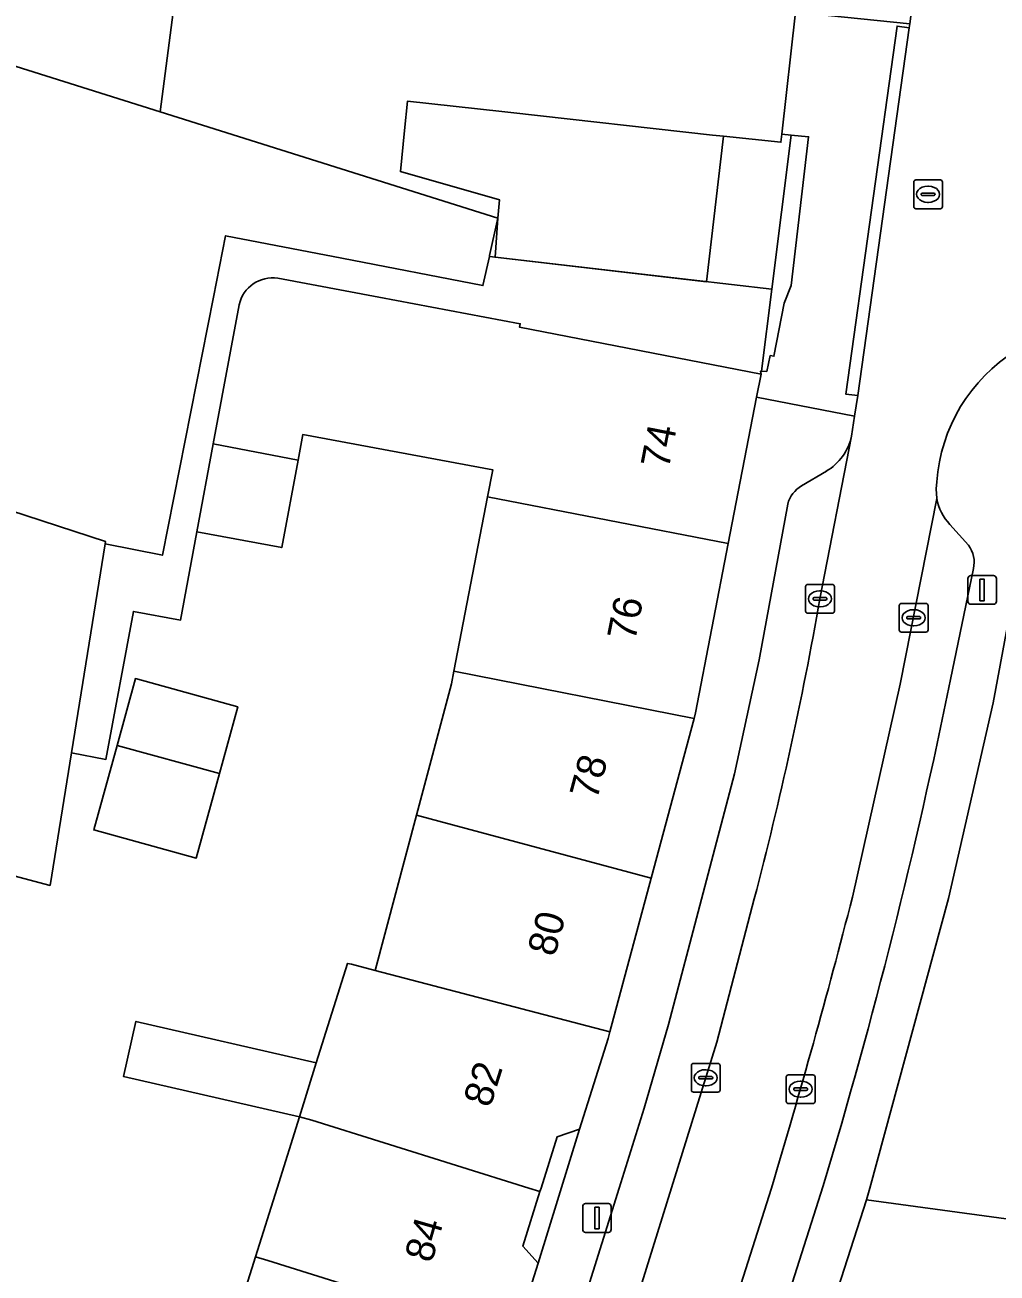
# Model space of a CAD drawing. Extents: x 161838 to 162344, y 381620 to 382160.
# Drawn here: x 161903.48 to 161937.3, y 381747.04 to 381790.47 of the extents above; entities that cross this region are included whole.
import ezdxf

# ---------------------------------------------------------------- set-up
doc = ezdxf.new("R2010")
doc.units = 0
for name, color, linetype in [('IMGEO_Erf', 7, 'Continuous'), ('IMGEO_Kolk', 7, 'Continuous'), ('IMGEO_Lichtmast', 7, 'Continuous'), ('IMGEO_Pand', 7, 'Continuous'), ('IMGEO_Pand_nummerreeks', 7, 'Continuous'), ('IMGEO_Pand_overbouw', 7, 'Continuous'), ('IMGEO_Parkeervlak_open', 7, 'Continuous'), ('IMGEO_Rijbaan_lokaal_open', 7, 'Continuous'), ('IMGEO_Rioolput', 7, 'Continuous'), ('IMGEO_Voetpad_open', 7, 'Continuous')]:
    doc.layers.add(name, color=color, linetype=linetype)

msp = doc.modelspace()

# ---------------------------------------------------------------- linework, layer by layer
at = {"layer": 'IMGEO_Erf'}
for points in [[(161930.143, 381786.634), (161929.815, 381786.663), (161929.784, 381786.389), (161927.782, 381786.601), (161927.396, 381786.639), (161920.39, 381787.417), (161920.074, 381787.452), (161916.79, 381787.816), (161916.687, 381786.798), (161916.543, 381785.369), (161919.986, 381784.388), (161919.939, 381783.745), (161919.647, 381782.443), (161919.639, 381782.409), (161929.463, 381781.27)], [(161905.878, 381762.46), (161906.688, 381765.402), (161907.326, 381767.725), (161910.889, 381766.746), (161910.25, 381764.423), (161909.441, 381761.48)], [(161921.4, 381749.878), (161920.799, 381747.972), (161921.338, 381747.387), (161922.777, 381752.053), (161922.002, 381751.786), (161921.439, 381750)]]:
    msp.add_lwpolyline(points, close=True, dxfattribs=at)
for points in [[(162000, 381769.681), (161974.073, 381772.99), (161973.465, 381773.068), (161939.385, 381777.509), (161939.117, 381777.363), (161937.166, 381766.879), (161935.609, 381760.072), (161932.874, 381750), (161932.761, 381749.584), (161940.003, 381748.598), (161940.179, 381750), (161940.747, 381754.512), (161939.055, 381754.703), (161940.656, 381766.246), (161941.27, 381771.689), (161943.773, 381771.406), (161958.15, 381769.783), (161958.302, 381771.128), (161966.661, 381770.185), (161965.98, 381765.232), (161963.918, 381750), (161962.379, 381738.634)], [(161910.729, 381745.136), (161911.501, 381747.601), (161912.253, 381750), (161913.031, 381752.482), (161906.907, 381753.886), (161907.345, 381755.798), (161913.619, 381754.359), (161914.701, 381757.815), (161914.848, 381757.787), (161915.662, 381757.574), (161917.1, 381762.969), (161918.319, 381767.543), (161918.404, 381767.982), (161919.577, 381774.046), (161919.76, 381774.989), (161913.149, 381776.217), (161912.983, 381775.322), (161912.418, 381772.284), (161909.468, 381772.836), (161908.896, 381769.76), (161907.257, 381770.065), (161906.301, 381764.916), (161905.101, 381765.139), (161904.357, 381760.527), (161891.624, 381763.915)]]:
    msp.add_lwpolyline(points, dxfattribs=at)
at = {"layer": 'IMGEO_Kolk'}
for p, q in [((161930.714, 381771.001), (161931.566, 381771.001)), ((161930.639, 381770.075), (161930.639, 381770.927)), ((161931.127, 381770.781), (161931.152, 381770.781)), ((161931.64, 381770.927), (161931.64, 381770.075)), ((161930.898, 381770.495), (161930.898, 381770.507)), ((161931.336, 381770.458), (161930.938, 381770.458)), ((161930.941, 381770.544), (161931.339, 381770.544)), ((161931.15, 381770.221), (161931.125, 381770.221)), ((161931.382, 381770.507), (161931.382, 381770.495)), ((161933.898, 381769.417), (161933.898, 381770.269)), ((161933.973, 381770.343), (161934.825, 381770.343)), ((161934.899, 381770.269), (161934.899, 381769.417)), ((161931.566, 381770.001), (161930.714, 381770.001)), ((161934.157, 381769.837), (161934.157, 381769.849)), ((161934.595, 381769.8), (161934.197, 381769.8)), ((161934.2, 381769.886), (161934.598, 381769.886)), ((161934.386, 381770.123), (161934.411, 381770.123)), ((161934.641, 381769.849), (161934.641, 381769.837)), ((161934.825, 381769.343), (161933.973, 381769.343)), ((161934.409, 381769.563), (161934.384, 381769.563)), ((161926.665, 381753.411), (161926.665, 381754.263)), ((161926.74, 381754.337), (161927.592, 381754.337)), ((161927.153, 381754.117), (161927.178, 381754.117)), ((161927.666, 381754.263), (161927.666, 381753.411)), ((161926.924, 381753.831), (161926.924, 381753.843)), ((161927.362, 381753.794), (161926.964, 381753.794)), ((161926.967, 381753.88), (161927.365, 381753.88)), ((161927.408, 381753.843), (161927.408, 381753.831)), ((161929.967, 381753.013), (161929.967, 381753.865)), ((161930.042, 381753.939), (161930.894, 381753.939)), ((161930.455, 381753.719), (161930.48, 381753.719)), ((161930.968, 381753.865), (161930.968, 381753.013)), ((161927.592, 381753.337), (161926.74, 381753.337)), ((161927.176, 381753.557), (161927.151, 381753.557)), ((161930.226, 381753.433), (161930.226, 381753.445)), ((161930.664, 381753.396), (161930.266, 381753.396)), ((161930.269, 381753.482), (161930.667, 381753.482)), ((161930.71, 381753.445), (161930.71, 381753.433)), ((161930.894, 381752.939), (161930.042, 381752.939)), ((161930.478, 381753.159), (161930.453, 381753.159))]:
    msp.add_line(p, q, dxfattribs=at)
for points in [[(161930.714, 381771.001), (161931.566, 381771.001)], [(161930.639, 381770.075), (161930.639, 381770.927)], [(161931.64, 381770.927), (161931.64, 381770.075)], [(161933.898, 381769.417), (161933.898, 381770.269)], [(161933.973, 381770.343), (161934.825, 381770.343)], [(161934.899, 381770.269), (161934.899, 381769.417)], [(161931.566, 381770.001), (161930.714, 381770.001)], [(161934.825, 381769.343), (161933.973, 381769.343)], [(161926.665, 381753.411), (161926.665, 381754.263)], [(161926.74, 381754.337), (161927.592, 381754.337)], [(161927.666, 381754.263), (161927.666, 381753.411)], [(161929.967, 381753.013), (161929.967, 381753.865)], [(161930.042, 381753.939), (161930.894, 381753.939)], [(161930.968, 381753.865), (161930.968, 381753.013)], [(161927.592, 381753.337), (161926.74, 381753.337)], [(161930.894, 381752.939), (161930.042, 381752.939)]]:
    msp.add_lwpolyline(points, dxfattribs=at)
for centre, radius, start, end in [((161930.716, 381770.925), 0.0765, 91.552, 178.448), ((161930.716, 381770.925), 0.0765, 91.552, 178.448), ((161931.564, 381770.925), 0.0765, 1.552, 88.448), ((161931.564, 381770.925), 0.0765, 1.552, 88.448), ((161930.938, 381770.504), 0.0403, 85.8775, 175.7526), ((161930.935, 381770.494), 0.0366, 178.938, 274.7102), ((161931.339, 381770.501), 0.043, 264.8664, 352.4533), ((161931.343, 381770.506), 0.0386, 1.7309, 96.639), ((161933.975, 381770.267), 0.0765, 91.552, 178.448), ((161933.975, 381770.267), 0.0765, 91.552, 178.448), ((161934.823, 381770.267), 0.0765, 1.552, 88.448), ((161934.823, 381770.267), 0.0765, 1.552, 88.448), ((161930.716, 381770.077), 0.0765, 181.552, 268.448), ((161930.716, 381770.077), 0.0765, 181.552, 268.448), ((161931.564, 381770.077), 0.0765, 271.552, 358.448), ((161931.564, 381770.077), 0.0765, 271.552, 358.448), ((161934.197, 381769.846), 0.0403, 85.8775, 175.7526), ((161934.194, 381769.836), 0.0366, 178.938, 274.7102), ((161934.598, 381769.843), 0.043, 264.8664, 352.4533), ((161934.602, 381769.848), 0.0386, 1.7309, 96.639), ((161933.975, 381769.419), 0.0765, 181.552, 268.448), ((161933.975, 381769.419), 0.0765, 181.552, 268.448), ((161934.823, 381769.419), 0.0765, 271.552, 358.448), ((161934.823, 381769.419), 0.0765, 271.552, 358.448), ((161926.742, 381754.261), 0.0765, 91.552, 178.448), ((161926.742, 381754.261), 0.0765, 91.552, 178.448), ((161927.59, 381754.261), 0.0765, 1.552, 88.448), ((161927.59, 381754.261), 0.0765, 1.552, 88.448), ((161926.964, 381753.84), 0.0403, 85.8775, 175.7526), ((161926.961, 381753.83), 0.0366, 178.938, 274.7102), ((161927.365, 381753.837), 0.043, 264.8664, 352.4533), ((161927.369, 381753.842), 0.0386, 1.7309, 96.639), ((161930.044, 381753.863), 0.0765, 91.552, 178.448), ((161930.044, 381753.863), 0.0765, 91.552, 178.448), ((161930.892, 381753.863), 0.0765, 1.552, 88.448), ((161930.892, 381753.863), 0.0765, 1.552, 88.448), ((161926.742, 381753.413), 0.0765, 181.552, 268.448), ((161926.742, 381753.413), 0.0765, 181.552, 268.448), ((161927.59, 381753.413), 0.0765, 271.552, 358.448), ((161927.59, 381753.413), 0.0765, 271.552, 358.448), ((161930.266, 381753.442), 0.0403, 85.8775, 175.7526), ((161930.263, 381753.432), 0.0366, 178.938, 274.7102), ((161930.667, 381753.439), 0.043, 264.8664, 352.4533), ((161930.671, 381753.444), 0.0386, 1.7309, 96.639), ((161930.044, 381753.015), 0.0765, 181.552, 268.448), ((161930.044, 381753.015), 0.0765, 181.552, 268.448), ((161930.892, 381753.015), 0.0765, 271.552, 358.448), ((161930.892, 381753.015), 0.0765, 271.552, 358.448)]:
    msp.add_arc(centre, radius, start, end, dxfattribs=at)
for centre, major_axis, ratio, start_param, end_param in [((161931.126, 381770.501), (-0.387, 0.002), 0.722429, 4.712389, 7.853982), ((161931.151, 381770.501), (-0.39, 0.002), 0.717154, 1.570796, 4.712389), ((161934.385, 381769.843), (-0.387, 0.002), 0.722429, 4.712389, 7.853982), ((161934.41, 381769.843), (-0.39, 0.002), 0.717154, 1.570796, 4.712389), ((161927.152, 381753.837), (-0.387, 0.002), 0.722429, 4.712389, 7.853982), ((161927.177, 381753.837), (-0.39, 0.002), 0.717154, 1.570796, 4.712389), ((161930.454, 381753.439), (-0.387, 0.002), 0.722429, 4.712389, 7.853982), ((161930.479, 381753.439), (-0.39, 0.002), 0.717154, 1.570796, 4.712389)]:
    msp.add_ellipse(centre, major_axis=major_axis, ratio=ratio, start_param=start_param, end_param=end_param, dxfattribs=at)
at = {"layer": 'IMGEO_Lichtmast'}
for p, q in [((161936.286, 381770.41), (161936.286, 381771.21)), ((161936.286, 381771.21), (161936.286, 381770.41)), ((161936.386, 381771.31), (161937.176, 381771.31)), ((161937.176, 381771.31), (161936.386, 381771.31)), ((161937.276, 381771.21), (161937.276, 381770.41)), ((161937.276, 381770.41), (161937.276, 381771.21)), ((161937.176, 381770.31), (161936.386, 381770.31)), ((161936.386, 381770.31), (161937.176, 381770.31)), ((161922.888, 381748.558), (161922.888, 381749.358)), ((161922.888, 381749.358), (161922.888, 381748.558)), ((161922.988, 381749.458), (161923.778, 381749.458)), ((161923.778, 381749.458), (161922.988, 381749.458)), ((161923.878, 381749.358), (161923.878, 381748.558)), ((161923.878, 381748.558), (161923.878, 381749.358)), ((161923.778, 381748.458), (161922.988, 381748.458)), ((161922.988, 381748.458), (161923.778, 381748.458))]:
    msp.add_line(p, q, dxfattribs=at)
for points in [[(161936.706, 381771.185), (161936.856, 381771.185), (161936.856, 381770.435), (161936.706, 381770.435), (161936.706, 381771.185)], [(161923.308, 381749.333), (161923.458, 381749.333), (161923.458, 381748.583), (161923.308, 381748.583), (161923.308, 381749.333)]]:
    msp.add_lwpolyline(points, dxfattribs=at)
for centre, start, end in [((161936.386, 381771.21), 90, 180), ((161936.386, 381771.21), 90, 180), ((161937.176, 381771.21), 0, 90), ((161937.176, 381771.21), 360, 90), ((161936.386, 381770.41), 180, 270), ((161936.386, 381770.41), 180, 270), ((161937.176, 381770.41), 270, 0), ((161937.176, 381770.41), 270, 0), ((161922.988, 381749.358), 90, 180), ((161922.988, 381749.358), 90, 180), ((161923.778, 381749.358), 0, 90), ((161923.778, 381749.358), 360, 90), ((161922.988, 381748.558), 180, 270), ((161922.988, 381748.558), 180, 270), ((161923.778, 381748.558), 270, 0), ((161923.778, 381748.558), 270, 0)]:
    msp.add_arc(centre, 0.1, start, end, dxfattribs=at)
at = {"layer": 'IMGEO_Pand'}
for points in [[(161911.591, 381813.594), (161887.08, 381818.184), (161882.7, 381795.067), (161891.426, 381793.391), (161891.237, 381792.79), (161908.185, 381787.449)], [(161919.939, 381783.745), (161908.185, 381787.449), (161891.237, 381792.79), (161891.426, 381793.391), (161882.7, 381795.067), (161881.558, 381789.042), (161880.152, 381781.62), (161884.545, 381780.782), (161884.571, 381780.917), (161887.782, 381780.305), (161887.441, 381778.645), (161906.287, 381772.495), (161906.273, 381772.411), (161908.264, 381772.019), (161910.041, 381780.996), (161910.464, 381783.132), (161914.505, 381782.351), (161919.414, 381781.401), (161919.639, 381782.409), (161919.647, 381782.443)], [(161887.441, 381778.645), (161887.782, 381780.305), (161884.571, 381780.917), (161884.545, 381780.782), (161880.152, 381781.62), (161880.122, 381781.461), (161877.48, 381767.677), (161886.792, 381765.2), (161891.624, 381763.915), (161904.357, 381760.527), (161905.101, 381765.139), (161906.273, 381772.411), (161906.287, 381772.495)], [(161910.036, 381775.892), (161909.468, 381772.836), (161912.418, 381772.284), (161912.983, 381775.322)], [(161926.758, 381766.342), (161926.809, 381766.533), (161927.949, 381772.425), (161919.577, 381774.046), (161918.404, 381767.982)], [(161943.773, 381771.406), (161941.27, 381771.689), (161940.656, 381766.246), (161939.055, 381754.703), (161940.747, 381754.512), (161940.179, 381750), (161940.003, 381748.598), (161932.761, 381749.584), (161928.68, 381736.917), (161933.635, 381736.242), (161961.501, 381732.448), (161962.379, 381738.634), (161963.918, 381750), (161965.98, 381765.232), (161966.661, 381770.185), (161958.302, 381771.128), (161958.15, 381769.783)], [(161926.758, 381766.342), (161918.404, 381767.982), (161918.319, 381767.543), (161917.1, 381762.969), (161925.266, 381760.778)], [(161906.688, 381765.402), (161910.25, 381764.423), (161910.889, 381766.746), (161907.326, 381767.725)], [(161910.25, 381764.423), (161906.688, 381765.402), (161905.878, 381762.46), (161909.441, 381761.48)], [(161925.266, 381760.778), (161917.1, 381762.969), (161915.662, 381757.574), (161923.832, 381755.432)], [(161923.772, 381755.207), (161923.832, 381755.432), (161915.662, 381757.574), (161914.848, 381757.787), (161914.701, 381757.815), (161913.619, 381754.359), (161913.031, 381752.482), (161913.46, 381752.366), (161921.01, 381750), (161921.4, 381749.878), (161921.439, 381750), (161922.002, 381751.786), (161922.777, 381752.053)], [(161913.619, 381754.359), (161907.345, 381755.798), (161906.907, 381753.886), (161913.031, 381752.482)], [(161911.501, 381747.601), (161911.931, 381747.484), (161919.889, 381744.99), (161919.975, 381745.264), (161920.725, 381745.432), (161921.338, 381747.387), (161920.799, 381747.972), (161921.4, 381749.878), (161921.01, 381750), (161913.46, 381752.366), (161913.031, 381752.482), (161912.253, 381750)], [(161919.803, 381744.714), (161919.889, 381744.99), (161911.931, 381747.484), (161911.501, 381747.601), (161910.729, 381745.136), (161907.818, 381745.978), (161907.547, 381745.04), (161900.603, 381746.898), (161900.186, 381745.198), (161904.185, 381744.088), (161904.269, 381744.065), (161907.187, 381743.221), (161910.351, 381742.442), (161918.278, 381739.958), (161918.886, 381741.9), (161919.673, 381742.076), (161920.239, 381743.88)]]:
    msp.add_lwpolyline(points, close=True, dxfattribs=at)
for points in [[(161911.591, 381813.594), (161908.185, 381787.449), (161919.939, 381783.745), (161919.986, 381784.388), (161916.543, 381785.369), (161916.687, 381786.798), (161916.79, 381787.816), (161920.074, 381787.452), (161920.39, 381787.417), (161927.396, 381786.639), (161927.782, 381786.601), (161929.784, 381786.389), (161929.815, 381786.663), (161930.291, 381790.911)], [(161910.936, 381780.734), (161910.036, 381775.892), (161912.983, 381775.322), (161913.149, 381776.217), (161919.76, 381774.989), (161919.577, 381774.046), (161927.949, 381772.425), (161928.936, 381777.521), (161929.089, 381778.313), (161920.692, 381779.951), (161920.712, 381780.075), (161915.798, 381780.995), (161912.276, 381781.655)]]:
    msp.add_lwpolyline(points, dxfattribs=at)
msp.add_arc((161912.101, 381780.474), 1.194, 81.5709, 167.4317, dxfattribs=at)
at = {"layer": 'IMGEO_Pand_overbouw'}
msp.add_lwpolyline([(161927.782, 381786.601), (161927.396, 381786.639), (161920.39, 381787.417), (161920.074, 381787.452), (161916.79, 381787.816), (161916.687, 381786.798), (161916.543, 381785.369), (161919.986, 381784.388), (161919.939, 381783.745), (161919.841, 381782.386), (161927.196, 381781.533)], close=True, dxfattribs=at)
at = {"layer": 'IMGEO_Parkeervlak_open'}
for points in [[(161931.14, 381770.501), (161932.238, 381776.158)], [(161931.361, 381774.946), (161930.496, 381774.433)], [(161930.019, 381773.8), (161929.028, 381768.381), (161928.167, 381764.412), (161925.871, 381755.689), (161925.028, 381752.783), (161924.159, 381750), (161919.692, 381735.743), (161915.985, 381722.354)], [(161935.205, 381773.992), (161933.932, 381767.536), (161932.268, 381760.122)], [(161936.306, 381772.368), (161935.66, 381773.092)], [(161935.677, 381767.694), (161936.478, 381771.553)], [(161916.883, 381719.321), (161919.084, 381727.401), (161920.816, 381733.424), (161927.557, 381755.075), (161928.855, 381760.062)], [(161929.449, 381750), (161922.839, 381729.219)], [(161922.974, 381718.936), (161923.837, 381725.942), (161924.196, 381727.931), (161931.251, 381750.082)]]:
    msp.add_lwpolyline(points, dxfattribs=at)
for centre, radius, start, end in [((161930.448, 381776.53), 1.828, 299.9604, 348.2608), ((161931.031, 381773.533), 1.047, 120.7588, 165.2412), ((161936.856, 381774.262), 1.673, 189.2735, 224.3648), ((161935.503, 381771.773), 1, 347.2919, 36.5421), ((161801.04, 381793.509), 132.119, 345.33547, 349.97097), ((161747.103, 381805.722), 192.37, 343.18801, 348.5987), ((161691.62, 381821.689), 248.398, 343.22547, 345.64925)]:
    msp.add_arc(centre, radius, start, end, dxfattribs=at)
at = {"layer": 'IMGEO_Rijbaan_lokaal_open'}
for points in [[(161938.055, 381792.981), (161938.12, 381793.764), (161939.514, 381810.412), (161939.516, 381810.43), (161940.145, 381818.394), (161936.924, 381818.645), (161936.567, 381814.112), (161935.814, 381803.997), (161934.702, 381793.974), (161934.263, 381790.508), (161934.246, 381790.374), (161932.457, 381777.573), (161932.346, 381776.852), (161932.238, 381776.158), (161931.14, 381770.501)], [(161932.268, 381760.122), (161933.932, 381767.536), (161935.205, 381773.992), (161935.184, 381774.328), (161935.21, 381774.572)], [(161928.855, 381760.062), (161927.557, 381755.075), (161920.816, 381733.424), (161919.084, 381727.401), (161916.883, 381719.321), (161916.695, 381718.702), (161921.068, 381717.499), (161922.182, 381726.301)], [(161922.839, 381729.219), (161929.449, 381750)]]:
    msp.add_lwpolyline(points, dxfattribs=at)
for centre, radius, start, end in [((161940.989, 381774.194), 5.792, 121.5017, 176.2572), ((161801.04, 381793.509), 132.119, 345.33547, 349.97097), ((161691.62, 381821.689), 248.398, 343.22547, 345.64925)]:
    msp.add_arc(centre, radius, start, end, dxfattribs=at)
at = {"layer": 'IMGEO_Rioolput'}
for p, q in [((161934.4, 381784.15), (161934.4, 381785.002)), ((161934.475, 381785.076), (161935.327, 381785.076)), ((161935.401, 381785.002), (161935.401, 381784.15)), ((161934.659, 381784.57), (161934.659, 381784.582)), ((161935.097, 381784.533), (161934.699, 381784.533)), ((161934.702, 381784.619), (161935.1, 381784.619)), ((161934.888, 381784.856), (161934.913, 381784.856)), ((161935.143, 381784.582), (161935.143, 381784.57)), ((161935.327, 381784.076), (161934.475, 381784.076)), ((161934.911, 381784.296), (161934.886, 381784.296))]:
    msp.add_line(p, q, dxfattribs=at)
for points in [[(161934.4, 381784.15), (161934.4, 381785.002)], [(161934.475, 381785.076), (161935.327, 381785.076)], [(161935.401, 381785.002), (161935.401, 381784.15)], [(161935.327, 381784.076), (161934.475, 381784.076)]]:
    msp.add_lwpolyline(points, dxfattribs=at)
for centre, radius, start, end in [((161934.477, 381785), 0.0765, 91.552, 178.448), ((161934.477, 381785), 0.0765, 91.552, 178.448), ((161935.325, 381785), 0.0765, 1.552, 88.448), ((161935.325, 381785), 0.0765, 1.552, 88.448), ((161934.699, 381784.579), 0.0403, 85.8775, 175.7526), ((161934.696, 381784.569), 0.0366, 178.938, 274.7102), ((161935.1, 381784.576), 0.043, 264.8664, 352.4533), ((161935.104, 381784.581), 0.0386, 1.7309, 96.639), ((161934.477, 381784.152), 0.0765, 181.552, 268.448), ((161934.477, 381784.152), 0.0765, 181.552, 268.448), ((161935.325, 381784.152), 0.0765, 271.552, 358.448), ((161935.325, 381784.152), 0.0765, 271.552, 358.448)]:
    msp.add_arc(centre, radius, start, end, dxfattribs=at)
for centre, major_axis, ratio, start_param, end_param in [((161934.887, 381784.576), (-0.387, 0.002), 0.722429, 4.712389, 7.853982), ((161934.912, 381784.576), (-0.39, 0.002), 0.717154, 1.570796, 4.712389)]:
    msp.add_ellipse(centre, major_axis=major_axis, ratio=ratio, start_param=start_param, end_param=end_param, dxfattribs=at)
at = {"layer": 'IMGEO_Voetpad_open'}
for points in [[(161934.246, 381790.374), (161934.263, 381790.508), (161930.291, 381790.911), (161929.815, 381786.663), (161930.143, 381786.634), (161930.743, 381786.58), (161930.141, 381781.399), (161929.896, 381780.786), (161929.539, 381778.94), (161929.41, 381778.964), (161929.289, 381778.413), (161929.102, 381778.419), (161929.072, 381778.42), (161929.089, 381778.313), (161928.936, 381777.521), (161932.346, 381776.852), (161932.457, 381777.573), (161932.035, 381777.628), (161933.822, 381790.429)], [(161934.246, 381790.374), (161933.822, 381790.429), (161932.035, 381777.628), (161932.457, 381777.573)], [(161930.743, 381786.58), (161930.143, 381786.634), (161929.463, 381781.27), (161929.102, 381778.419), (161929.289, 381778.413), (161929.41, 381778.964), (161929.539, 381778.94), (161929.896, 381780.786), (161930.141, 381781.399)]]:
    msp.add_lwpolyline(points, close=True, dxfattribs=at)
for points in [[(161929.463, 381781.27), (161919.639, 381782.409), (161919.414, 381781.401), (161914.505, 381782.351), (161910.464, 381783.132), (161910.041, 381780.996), (161908.264, 381772.019), (161906.273, 381772.411), (161905.101, 381765.139), (161906.301, 381764.916), (161907.257, 381770.065), (161908.896, 381769.76), (161909.468, 381772.836), (161910.036, 381775.892), (161910.936, 381780.734)], [(161912.276, 381781.655), (161915.798, 381780.995), (161920.712, 381780.075), (161920.692, 381779.951), (161929.089, 381778.313), (161929.072, 381778.42), (161929.102, 381778.419), (161929.463, 381781.27)], [(161924.676, 381720.871), (161925.447, 381726.604), (161928.204, 381735.395), (161928.68, 381736.917), (161932.761, 381749.584), (161932.874, 381750), (161935.609, 381760.072), (161937.166, 381766.879), (161939.117, 381777.363), (161939.385, 381777.509), (161937.963, 381779.132)], [(161932.238, 381776.158), (161932.346, 381776.852), (161928.936, 381777.521), (161927.949, 381772.425), (161926.809, 381766.533), (161926.758, 381766.342), (161925.266, 381760.778), (161923.832, 381755.432), (161923.772, 381755.207), (161922.777, 381752.053), (161921.338, 381747.387), (161920.725, 381745.432), (161920.239, 381743.88), (161919.673, 381742.076), (161918.217, 381737.419), (161917.325, 381734.571), (161917.032, 381733.501), (161914.271, 381722.897), (161912.504, 381716.211), (161915.172, 381715.818), (161916.534, 381718.098), (161916.581, 381718.326), (161916.695, 381718.702), (161916.883, 381719.321)], [(161930.496, 381774.433), (161931.361, 381774.946)], [(161935.21, 381774.572), (161935.184, 381774.328), (161935.205, 381773.992)], [(161924.159, 381750), (161925.028, 381752.783), (161925.871, 381755.689), (161928.167, 381764.412), (161929.028, 381768.381), (161930.019, 381773.8)], [(161935.66, 381773.092), (161936.306, 381772.368)], [(161936.478, 381771.553), (161935.677, 381767.694)], [(161915.985, 381722.354), (161919.692, 381735.743), (161924.159, 381750)], [(161931.251, 381750.082), (161924.196, 381727.931), (161923.837, 381725.942), (161922.974, 381718.936)]]:
    msp.add_lwpolyline(points, dxfattribs=at)
for centre, radius, start, end in [((161912.101, 381780.474), 1.194, 81.5709, 167.4317), ((161940.989, 381774.194), 5.792, 121.5017, 176.2572), ((161930.448, 381776.53), 1.828, 299.9604, 348.2608), ((161931.031, 381773.533), 1.047, 120.7588, 165.2412), ((161936.856, 381774.262), 1.673, 189.2735, 224.3648), ((161935.503, 381771.773), 1, 347.2919, 36.5421), ((161747.103, 381805.722), 192.37, 343.18801, 348.5987)]:
    msp.add_arc(centre, radius, start, end, dxfattribs=at)

# ---------------------------------------------------------------- texts
at = {"layer": 'IMGEO_Pand_nummerreeks'}
for s, rotation, p in [('74', 78.9802, (161925.875, 381774.991)), ('76', 78.9802, (161924.709, 381769.005)), ('78', 74.9831, (161923.378, 381763.473)), ('80', 74.983, (161921.915, 381758.018)), ('82', 72.4963, (161919.668, 381752.766)), ('84', 74.0341, (161917.634, 381747.362))]:
    msp.add_text(s, height=1, rotation=rotation, dxfattribs=at).set_placement(p)

doc.saveas('drawing.dxf')
